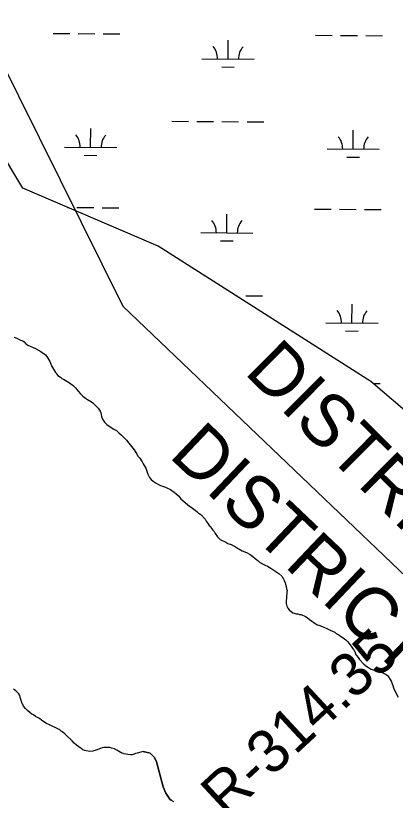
# Model space of a CAD drawing. Extents: x 3172231 to 3210228, y 940198 to 965780.
# Drawn here: x 3194127 to 3194853, y 949300 to 950801 of the extents above; entities that cross this region are included whole.
import ezdxf

# ---------------------------------------------------------------- set-up
doc = ezdxf.new("R2010")
doc.units = 0
for name, color, linetype in [('V-RIVR-RANG-IDEN', 7, 'Continuous'), ('V-SITE-VEGE', 7, 'Continuous'), ('V-TOPO-BNDY', 7, 'Continuous'), ('V-TOPO-GNAM-IDEN', 7, 'Continuous'), ('V-TOPO-SHOR', 7, 'Continuous'), ('V-WETL-SWMP', 7, 'Continuous')]:
    doc.layers.add(name, color=color, linetype=linetype)

msp = doc.modelspace()

# ---------------------------------------------------------------- linework, layer by layer
at = {"layer": 'V-SITE-VEGE'}
for p, q in [((3194124.25, 950186.368), (3194129.438, 950184.349)), ((3194129.438, 950184.349), (3194136.364, 950180.624)), ((3194136.364, 950180.624), (3194140.515, 950178.94)), ((3194140.515, 950178.94), (3194143.29, 950176.898)), ((3194143.29, 950176.898), (3194146.77, 950173.484)), ((3194146.77, 950173.484), (3194150.237, 950171.107)), ((3194150.237, 950171.107), (3194165.118, 950164.352)), ((3194165.118, 950164.352), (3194175.159, 950158.933)), ((3194175.159, 950158.933), (3194181.408, 950154.168)), ((3194181.408, 950154.168), (3194183.839, 950152.124)), ((3194183.839, 950152.124), (3194186.626, 950149.048)), ((3194186.626, 950149.048), (3194192.223, 950139.797)), ((3194192.223, 950139.797), (3194195.748, 950131.216)), ((3194195.748, 950131.216), (3194197.505, 950127.785)), ((3194197.505, 950127.785), (3194201.351, 950121.619)), ((3194201.351, 950121.619), (3194203.448, 950118.537)), ((3194203.448, 950118.537), (3194204.843, 950116.826)), ((3194204.843, 950116.826), (3194205.197, 950115.796)), ((3194205.197, 950115.796), (3194207.978, 950113.066)), ((3194207.978, 950113.066), (3194212.492, 950109.319)), ((3194212.492, 950109.319), (3194215.269, 950107.277)), ((3194215.269, 950107.277), (3194218.73, 950105.585)), ((3194218.73, 950105.585), (3194228.086, 950100.16)), ((3194228.086, 950100.16), (3194232.593, 950097.1)), ((3194232.593, 950097.1), (3194237.105, 950093.696)), ((3194237.105, 950093.696), (3194239.542, 950090.962)), ((3194239.542, 950090.962), (3194242.321, 950088.576)), ((3194242.321, 950088.576), (3194244.07, 950085.836)), ((3194244.07, 950085.836), (3194246.51, 950082.76)), ((3194246.51, 950082.76), (3194251.036, 950077.632)), ((3194251.036, 950077.632), (3194255.56, 950073.196)), ((3194255.56, 950073.196), (3194260.417, 950069.45)), ((3194260.417, 950069.45), (3194264.577, 950066.732)), ((3194264.577, 950066.732), (3194272.198, 950062.667)), ((3194272.198, 950062.667), (3194274.629, 950060.623)), ((3194274.629, 950060.623), (3194282.976, 950052.429)), ((3194282.976, 950052.429), (3194285.063, 950050.039)), ((3194285.063, 950050.039), (3194288.907, 950044.217)), ((3194288.907, 950044.217), (3194289.626, 950041.122)), ((3194289.626, 950041.122), (3194290.689, 950038.032)), ((3194290.689, 950038.032), (3194291.412, 950034.247)), ((3194291.412, 950034.247), (3194293.185, 950029.096)), ((3194293.185, 950029.096), (3194296.686, 950023.27)), ((3194296.686, 950023.27), (3194301.203, 950019.178)), ((3194301.203, 950019.178), (3194305.715, 950015.774)), ((3194305.715, 950015.774), (3194315.068, 950010.349)), ((3194315.068, 950010.349), (3194319.924, 950007.291)), ((3194319.924, 950007.291), (3194324.096, 950003.195)), ((3194324.096, 950003.195), (3194329.652, 949998.423)), ((3194329.652, 949998.423), (3194332.437, 949995.349)), ((3194332.437, 949995.349), (3194339.046, 949988.863)), ((3194339.046, 949988.863), (3194343.577, 949983.391)), ((3194343.577, 949983.391), (3194353.692, 949970.392)), ((3194353.692, 949970.392), (3194358.932, 949962.518)), ((3194358.932, 949962.518), (3194361.388, 949958.059)), ((3194361.388, 949958.059), (3194364.523, 949954.299)), ((3194364.523, 949954.299), (3194368.72, 949947.793)), ((3194368.72, 949947.793), (3194370.827, 949943.674)), ((3194370.827, 949943.674), (3194375.722, 949935.796)), ((3194375.722, 949935.796), (3194379.969, 949923.776)), ((3194379.969, 949923.776), (3194382.781, 949917.943)), ((3194382.781, 949917.943), (3194386.267, 949913.499)), ((3194386.267, 949913.499), (3194389.738, 949910.773)), ((3194389.738, 949910.773), (3194395.635, 949906.693)), ((3194395.635, 949906.693), (3194400.136, 949904.324)), ((3194400.136, 949904.324), (3194403.943, 949902.634)), ((3194403.943, 949902.634), (3194413.622, 949899.28)), ((3194413.622, 949899.28), (3194417.432, 949897.248)), ((3194417.432, 949897.248), (3194422.967, 949894.891)), ((3194422.967, 949894.891), (3194429.906, 949889.783)), ((3194429.906, 949889.783), (3194433.035, 949886.711)), ((3194433.035, 949886.711), (3194438.243, 949882.625)), ((3194438.243, 949882.625), (3194440.687, 949879.205)), ((3194440.687, 949879.205), (3194443.122, 949876.813)), ((3194443.122, 949876.813), (3194455.285, 949865.899)), ((3194455.285, 949865.899), (3194459.446, 949862.838)), ((3194459.446, 949862.838), (3194462.567, 949860.8)), ((3194462.567, 949860.8), (3194467.427, 949857.054)), ((3194467.427, 949857.054), (3194470.198, 949855.358)), ((3194470.198, 949855.358), (3194474.366, 949851.95)), ((3194474.366, 949851.95), (3194476.801, 949849.56)), ((3194476.801, 949849.56), (3194478.185, 949848.885)), ((3194478.185, 949848.885), (3194480.96, 949846.845)), ((3194480.96, 949846.845), (3194489.316, 949837.619)), ((3194489.316, 949837.619), (3194491.071, 949834.188)), ((3194491.071, 949834.188), (3194494.907, 949829.056)), ((3194494.907, 949829.056), (3194497.007, 949825.976)), ((3194497.007, 949825.976), (3194499.444, 949823.586)), ((3194499.444, 949823.586), (3194501.891, 949819.471)), ((3194501.891, 949819.471), (3194504.328, 949816.739)), ((3194504.328, 949816.739), (3194506.763, 949814.349)), ((3194506.763, 949814.349), (3194508.52, 949810.577)), ((3194508.52, 949810.577), (3194512.715, 949804.412)), ((3194512.715, 949804.412), (3194517.929, 949799.292)), ((3194517.929, 949799.292), (3194528.662, 949793.879)), ((3194528.662, 949793.879), (3194532.82, 949791.506)), ((3194532.82, 949791.506), (3194539.042, 949789.497)), ((3194539.042, 949789.497), (3194544.928, 949786.449)), ((3194544.928, 949786.449), (3194545.278, 949786.109)), ((3194545.278, 949786.109), (3194549.087, 949783.734)), ((3194549.087, 949783.734), (3194560.171, 949777.633)), ((3194560.171, 949777.633), (3194568.132, 949773.918)), ((3194568.132, 949773.918), (3194575.402, 949770.194)), ((3194575.402, 949770.194), (3194580.606, 949766.455)), ((3194580.606, 949766.455), (3194584.776, 949762.703)), ((3194584.776, 949762.703), (3194589.98, 949758.961)), ((3194589.98, 949758.961), (3194593.111, 949755.889)), ((3194593.111, 949755.889), (3194598.999, 949752.498)), ((3194598.999, 949752.498), (3194604.191, 949750.134)), ((3194604.191, 949750.134), (3194608.692, 949747.765)), ((3194608.692, 949747.765), (3194614.928, 949744.031)), ((3194614.928, 949744.031), (3194630.186, 949733.836)), ((3194630.186, 949733.836), (3194635.746, 949728.72)), ((3194635.746, 949728.72), (3194638.546, 949724.268)), ((3194638.546, 949724.268), (3194640.303, 949720.493)), ((3194640.303, 949720.493), (3194642.068, 949716.031)), ((3194642.068, 949716.031), (3194644.202, 949708.814)), ((3194644.202, 949708.814), (3194644.929, 949704.685)), ((3194644.929, 949704.685), (3194645.996, 949701.248)), ((3194645.996, 949701.248), (3194645.335, 949698.142)), ((3194645.335, 949698.142), (3194644.477, 949679.527)), ((3194644.477, 949679.527), (3194644.506, 949676.427)), ((3194644.506, 949676.427), (3194645.585, 949671.612)), ((3194645.585, 949671.612), (3194647.69, 949667.495)), ((3194647.69, 949667.495), (3194649.783, 949664.759)), ((3194649.783, 949664.759), (3194656.728, 949658.965)), ((3194656.728, 949658.965), (3194659.837, 949658.306)), ((3194659.837, 949658.306), (3194663.294, 949656.96)), ((3194663.294, 949656.96), (3194666.399, 949656.645)), ((3194666.399, 949656.645), (3194669.508, 949655.637)), ((3194669.508, 949655.637), (3194672.612, 949655.324)), ((3194672.612, 949655.324), (3194680.919, 949651.611)), ((3194680.919, 949651.611), (3194684.382, 949649.575)), ((3194684.382, 949649.575), (3194688.55, 949646.169)), ((3194688.55, 949646.169), (3194693.406, 949642.77)), ((3194693.406, 949642.77), (3194696.877, 949640.046)), ((3194696.877, 949640.046), (3194703.809, 949635.63)), ((3194703.809, 949635.63), (3194706.916, 949634.971)), ((3194706.916, 949634.971), (3194715.215, 949631.946)), ((3194715.215, 949631.946), (3194723.177, 949627.887)), ((3194723.177, 949627.887), (3194728.365, 949625.868)), ((3194728.365, 949625.868), (3194732.522, 949623.494)), ((3194732.522, 949623.494), (3194737.024, 949621.469)), ((3194737.024, 949621.469), (3194739.797, 949619.427)), ((3194739.797, 949619.427), (3194744.647, 949616.715)), ((3194744.647, 949616.715), (3194748.114, 949614.335)), ((3194748.114, 949614.335), (3194751.579, 949612.3)), ((3194751.579, 949612.3), (3194755.743, 949609.236)), ((3194755.743, 949609.236), (3194758.522, 949606.854)), ((3194758.522, 949606.854), (3194761.303, 949604.122)), ((3194761.303, 949604.122), (3194764.441, 949600.36)), ((3194764.441, 949600.36), (3194770.023, 949592.831)), ((3194770.023, 949592.831), (3194772.123, 949589.405)), ((3194772.123, 949589.405), (3194774.558, 949587.015)), ((3194774.558, 949587.015), (3194776.319, 949582.896)), ((3194776.319, 949582.896), (3194777.038, 949579.806)), ((3194777.038, 949579.806), (3194778.787, 949577.064)), ((3194778.787, 949577.064), (3194781.922, 949573.302)), ((3194781.922, 949573.302), (3194784.714, 949569.537)), ((3194784.714, 949569.537), (3194792.721, 949560.653)), ((3194792.721, 949560.653), (3194798.622, 949556.229)), ((3194798.622, 949556.229), (3194806.943, 949550.792)), ((3194806.943, 949550.792), (3194810.398, 949549.793)), ((3194810.398, 949549.793), (3194817.301, 949548.478)), ((3194817.301, 949548.478), (3194828.717, 949543.759)), ((3194828.717, 949543.759), (3194830.441, 949543.432)), ((3194830.441, 949543.432), (3194835.287, 949541.064)), ((3194835.287, 949541.064), (3194837.722, 949538.676)), ((3194837.722, 949538.676), (3194839.815, 949536.284)), ((3194839.815, 949536.284), (3194842.959, 949531.488)), ((3194842.959, 949531.488), (3194844.714, 949528.059)), ((3194844.714, 949528.059), (3194848.241, 949519.476)), ((3194127.125, 949509.642), (3194122.962, 949512.703)), ((3194130.601, 949506.572), (3194127.125, 949509.642)), ((3194133.04, 949503.496), (3194130.601, 949506.572)), ((3194848.241, 949519.476), (3194849.312, 949515.351)), ((3194849.312, 949515.351), (3194850.719, 949512.263)), ((3194850.719, 949512.263), (3194858.096, 949497.515)), ((3194135.137, 949500.411), (3194133.04, 949503.496)), ((3194136.571, 949494.566), (3194135.137, 949500.411)), ((3194137.294, 949490.784), (3194136.571, 949494.566)), ((3194138.709, 949487.007), (3194137.294, 949490.784)), ((3194142.215, 949480.492), (3194138.709, 949487.007)), ((3194146.049, 949475.704), (3194142.215, 949480.492)), ((3194149.879, 949471.604), (3194146.049, 949475.704)), ((3194155.089, 949467.174), (3194149.879, 949471.604)), ((3194157.864, 949465.132), (3194155.089, 949467.174)), ((3194160.981, 949463.439), (3194157.864, 949465.132)), ((3194164.794, 949460.719), (3194160.981, 949463.439)), ((3194168.61, 949458.341), (3194164.794, 949460.719)), ((3194172.419, 949456.31), (3194168.61, 949458.341)), ((3194176.935, 949452.562), (3194172.419, 949456.31)), ((3194180.052, 949450.866), (3194176.935, 949452.562)), ((3194184.904, 949447.81), (3194180.052, 949450.866)), ((3194192.866, 949443.751), (3194184.904, 949447.81)), ((3194207.747, 949436.999), (3194192.866, 949443.751)), ((3194211.214, 949434.619), (3194207.747, 949436.999)), ((3194214.69, 949431.549), (3194211.214, 949434.619)), ((3194217.809, 949429.512), (3194214.69, 949431.549)), ((3194220.932, 949427.13), (3194217.809, 949429.512)), ((3194223.711, 949424.742), (3194220.932, 949427.13)), ((3194234.84, 949413.82), (3194223.711, 949424.742)), ((3194239.018, 949409.382), (3194234.84, 949413.82)), ((3194243.188, 949405.628), (3194239.018, 949409.382)), ((3194247.695, 949402.568), (3194243.188, 949405.628)), ((3194252.205, 949399.164), (3194247.695, 949402.568)), ((3194295.606, 949400.948), (3194292.512, 949400.231)), ((3194307.321, 949401.059), (3194295.606, 949400.948)), ((3194310.432, 949400.053), (3194307.321, 949401.059)), ((3194255.674, 949396.784), (3194252.205, 949399.164)), ((3194258.443, 949395.433), (3194255.674, 949396.784)), ((3194261.554, 949394.427), (3194258.443, 949395.433)), ((3194269.144, 949393.465), (3194261.554, 949394.427)), ((3194274.309, 949393.858), (3194269.144, 949393.465)), ((3194281.18, 949395.99), (3194274.309, 949393.858)), ((3194289.075, 949399.164), (3194281.18, 949395.99)), ((3194292.512, 949400.231), (3194289.075, 949399.164)), ((3194315.957, 949398.726), (3194310.432, 949400.053)), ((3194320.463, 949396.012), (3194315.957, 949398.726)), ((3194326.703, 949391.937), (3194320.463, 949396.012)), ((3194330.164, 949390.245), (3194326.703, 949391.937)), ((3194332.927, 949389.582), (3194330.164, 949390.245)), ((3194333.275, 949389.24), (3194332.927, 949389.582)), ((3194337.764, 949388.248), (3194333.275, 949389.24)), ((3194341.557, 949387.941), (3194337.764, 949388.248)), ((3194346.735, 949386.954), (3194341.557, 949387.941)), ((3194349.831, 949387.329), (3194346.735, 949386.954)), ((3194353.616, 949388.052), (3194349.831, 949387.329)), ((3194356.36, 949389.457), (3194353.616, 949388.052)), ((3194359.451, 949390.52), (3194356.36, 949389.457)), ((3194366.33, 949391.961), (3194359.451, 949390.52)), ((3194370.95, 949393.37), (3194366.33, 949391.961)), ((3194384.317, 949390.163), (3194370.95, 949393.37)), ((3194392.409, 949382.145), (3194384.317, 949390.163)), ((3194396.29, 949373.538), (3194392.409, 949382.145)), ((3194409.373, 949325.844), (3194396.29, 949373.538)), ((3194414.413, 949313.658), (3194409.373, 949325.844)), ((3194421.681, 949302.505), (3194414.413, 949313.658)), ((3194424.364, 949300.086), (3194421.681, 949302.505))]:
    msp.add_line(p, q, dxfattribs=at)
at = {"layer": 'V-TOPO-BNDY'}
for p, q in [((3192802.44, 953324.154), (3194332.024, 950245.511)), ((3194332.024, 950245.511), (3197716.878, 947007.215))]:
    msp.add_line(p, q, dxfattribs=at)
at = {"layer": 'V-TOPO-SHOR'}
for points in [[(3194124.25, 950186.368), (3194129.438, 950184.349), (3194136.364, 950180.624), (3194140.515, 950178.94), (3194143.29, 950176.898), (3194146.77, 950173.484), (3194150.237, 950171.107), (3194165.118, 950164.352), (3194175.159, 950158.933), (3194181.408, 950154.168), (3194183.839, 950152.124), (3194186.624, 950149.048), (3194192.223, 950139.797), (3194195.75, 950131.216), (3194197.505, 950127.785), (3194201.351, 950121.619), (3194203.448, 950118.537), (3194204.843, 950116.826), (3194205.197, 950115.796), (3194207.978, 950113.066), (3194212.492, 950109.319), (3194215.269, 950107.277), (3194218.73, 950105.585), (3194228.086, 950100.16), (3194232.593, 950097.1), (3194237.105, 950093.696), (3194239.542, 950090.962), (3194242.321, 950088.576), (3194244.07, 950085.836), (3194246.51, 950082.758), (3194251.038, 950077.632), (3194255.56, 950073.196), (3194260.417, 950069.45), (3194264.577, 950066.732), (3194272.198, 950062.667), (3194274.629, 950060.623), (3194282.974, 950052.431), (3194285.063, 950050.039), (3194288.909, 950044.217), (3194289.626, 950041.122), (3194290.689, 950038.032), (3194291.414, 950034.247), (3194293.185, 950029.096), (3194296.686, 950023.27), (3194301.203, 950019.178), (3194305.715, 950015.774)], [(3194305.715, 950015.774), (3194315.068, 950010.349), (3194319.922, 950007.291), (3194324.096, 950003.195), (3194329.652, 949998.423), (3194332.437, 949995.349), (3194339.046, 949988.863), (3194343.577, 949983.391), (3194353.692, 949970.392), (3194358.932, 949962.518), (3194361.388, 949958.059), (3194364.523, 949954.299), (3194368.72, 949947.791), (3194370.825, 949943.676), (3194375.722, 949935.796), (3194379.969, 949923.776), (3194382.781, 949917.943), (3194386.267, 949913.497), (3194389.738, 949910.773), (3194395.635, 949906.693), (3194400.136, 949904.324), (3194403.943, 949902.634), (3194413.622, 949899.28), (3194417.432, 949897.248), (3194422.967, 949894.889), (3194429.906, 949889.783), (3194433.035, 949886.711), (3194438.243, 949882.625), (3194440.687, 949879.203), (3194443.122, 949876.813), (3194455.285, 949865.899), (3194459.446, 949862.838), (3194462.567, 949860.8), (3194467.427, 949857.054), (3194470.198, 949855.358), (3194474.366, 949851.95), (3194476.801, 949849.56), (3194478.185, 949848.885), (3194480.96, 949846.845), (3194489.316, 949837.619), (3194491.071, 949834.188), (3194494.909, 949829.056), (3194497.007, 949825.974), (3194499.442, 949823.586), (3194501.891, 949819.473), (3194504.328, 949816.739), (3194506.763, 949814.349), (3194508.52, 949810.577), (3194512.715, 949804.412), (3194517.931, 949799.292), (3194528.662, 949793.879), (3194532.82, 949791.506), (3194539.042, 949789.497), (3194544.928, 949786.449), (3194545.276, 949786.109), (3194549.087, 949783.734), (3194560.171, 949777.635), (3194568.132, 949773.918), (3194575.402, 949770.194), (3194580.606, 949766.455), (3194584.776, 949762.703), (3194589.98, 949758.961), (3194593.111, 949755.889), (3194598.999, 949752.498), (3194604.191, 949750.134), (3194608.692, 949747.765), (3194614.928, 949744.031), (3194630.186, 949733.836), (3194635.746, 949728.72), (3194638.546, 949724.268), (3194640.303, 949720.493), (3194642.068, 949716.031), (3194644.202, 949708.814), (3194644.929, 949704.685), (3194645.996, 949701.248), (3194645.335, 949698.142), (3194644.477, 949679.527), (3194644.506, 949676.427), (3194645.585, 949671.612), (3194647.69, 949667.495), (3194649.783, 949664.759), (3194656.728, 949658.965), (3194659.837, 949658.306), (3194663.294, 949656.96), (3194666.399, 949656.645), (3194669.51, 949655.639), (3194672.612, 949655.324), (3194672.612, 949655.324), (3194680.919, 949651.611), (3194684.382, 949649.575), (3194688.55, 949646.169), (3194693.406, 949642.77), (3194696.877, 949640.046), (3194703.809, 949635.63), (3194706.916, 949634.971), (3194715.215, 949631.946), (3194723.177, 949627.887), (3194728.365, 949625.868), (3194732.522, 949623.494), (3194737.022, 949621.469), (3194739.797, 949619.427)], [(3194739.797, 949619.427), (3194744.647, 949616.715), (3194748.116, 949614.335), (3194751.579, 949612.3), (3194755.743, 949609.238), (3194758.522, 949606.852), (3194761.303, 949604.122), (3194764.441, 949600.36), (3194770.023, 949592.831), (3194772.123, 949589.405), (3194774.558, 949587.015), (3194776.319, 949582.896), (3194777.038, 949579.804), (3194778.787, 949577.064), (3194781.922, 949573.302), (3194784.714, 949569.537), (3194792.721, 949560.653), (3194798.622, 949556.229), (3194806.943, 949550.792), (3194810.398, 949549.793), (3194817.301, 949548.478), (3194828.717, 949543.759), (3194830.441, 949543.432), (3194835.287, 949541.064), (3194837.722, 949538.676), (3194839.813, 949536.284), (3194842.959, 949531.488), (3194844.714, 949528.059), (3194848.241, 949519.476), (3194849.312, 949515.351), (3194850.719, 949512.263), (3194858.094, 949497.515)], [(3194370.95, 949393.37), (3194366.33, 949391.961), (3194359.451, 949390.52), (3194356.36, 949389.457), (3194353.616, 949388.052), (3194349.833, 949387.329), (3194346.735, 949386.954), (3194341.557, 949387.939), (3194337.764, 949388.248), (3194333.275, 949389.24), (3194332.927, 949389.582), (3194330.164, 949390.245), (3194326.703, 949391.937), (3194320.463, 949396.012), (3194315.957, 949398.726), (3194310.432, 949400.053), (3194307.321, 949401.059), (3194295.606, 949400.948), (3194292.512, 949400.231), (3194289.075, 949399.164), (3194281.18, 949395.99), (3194274.309, 949393.858), (3194269.144, 949393.465), (3194261.554, 949394.427), (3194258.443, 949395.433), (3194255.674, 949396.784), (3194252.205, 949399.164), (3194247.695, 949402.568), (3194243.188, 949405.628), (3194239.018, 949409.38), (3194234.84, 949413.82), (3194223.711, 949424.742), (3194220.932, 949427.13), (3194217.809, 949429.512), (3194214.69, 949431.549), (3194211.214, 949434.619), (3194207.747, 949436.999), (3194192.866, 949443.751), (3194184.904, 949447.81), (3194180.052, 949450.866), (3194176.935, 949452.562), (3194172.419, 949456.31), (3194168.61, 949458.341), (3194164.796, 949460.719), (3194160.981, 949463.439), (3194157.864, 949465.132), (3194155.089, 949467.174), (3194149.879, 949471.604), (3194146.049, 949475.704), (3194142.215, 949480.492), (3194138.709, 949487.007), (3194137.294, 949490.784), (3194136.571, 949494.566), (3194135.137, 949500.411), (3194133.04, 949503.493), (3194130.601, 949506.572), (3194127.125, 949509.642), (3194122.962, 949512.703)], [(3194370.95, 949393.37), (3194384.317, 949390.163), (3194392.409, 949382.145), (3194396.29, 949373.536), (3194409.373, 949325.844), (3194414.413, 949313.658), (3194421.681, 949302.503), (3194424.364, 949300.088), (3194428.616, 949297.641)]]:
    msp.add_lwpolyline(points, dxfattribs=at)
at = {"layer": 'V-WETL-SWMP'}
for p, q in [((3194140.824, 950470.858), (3193919.041, 950840.648)), ((3194198.521, 950767.073), (3194230.52, 950766.855)), ((3194246.52, 950766.746), (3194278.519, 950766.528)), ((3194294.519, 950766.419), (3194326.518, 950766.201)), ((3194533.041, 950718.365), (3194533.286, 950754.364)), ((3194700.418, 950763.656), (3194732.417, 950763.438)), ((3194748.416, 950763.329), (3194780.416, 950763.112)), ((3194796.415, 950763.003), (3194828.415, 950762.785)), ((3194483.043, 950718.705), (3194583.04, 950718.024)), ((3194520.937, 950703.016), (3194544.936, 950702.852)), ((3194425.383, 950599.024), (3194457.382, 950598.806)), ((3194473.381, 950598.697), (3194505.381, 950598.479)), ((3194521.38, 950598.37), (3194553.38, 950598.152)), ((3194569.379, 950598.043), (3194601.378, 950597.826)), ((3194270.449, 950549.335), (3194270.694, 950585.334)), ((3194772.345, 950545.919), (3194772.59, 950581.918)), ((3194220.45, 950549.675), (3194320.448, 950548.995)), ((3194722.346, 950546.259), (3194822.344, 950545.578)), ((3194258.344, 950533.986), (3194282.343, 950533.823)), ((3194760.24, 950530.57), (3194784.24, 950530.406)), ((3194399.57, 950359.921), (3194140.824, 950470.858)), ((3194226.322, 950434.201), (3194228.256, 950434.188)), ((3194244.256, 950434.079), (3194276.255, 950433.861)), ((3194292.254, 950433.752), (3194324.254, 950433.534)), ((3194530.777, 950385.697), (3194531.022, 950421.696)), ((3194698.153, 950430.989), (3194730.152, 950430.771)), ((3194746.152, 950430.662), (3194778.151, 950430.444)), ((3194794.151, 950430.335), (3194826.15, 950430.118)), ((3194480.778, 950386.038), (3194580.776, 950385.357)), ((3194518.672, 950370.348), (3194542.672, 950370.185)), ((3194806.172, 950101.067), (3194399.57, 950359.921)), ((3194547.873, 950265.507), (3194551.115, 950265.485)), ((3194567.115, 950265.376), (3194599.114, 950265.158)), ((3194770.081, 950213.251), (3194770.326, 950249.25)), ((3194720.082, 950213.592), (3194820.079, 950212.911)), ((3194757.976, 950197.902), (3194781.975, 950197.739)), ((3195064.919, 949879.193), (3194806.172, 950101.067)), ((3194810.282, 950097.543), (3194823.886, 950097.45))]:
    msp.add_line(p, q, dxfattribs=at)
for centre, start, end in [((3194477.803, 950719.215), 358.838165, 40.381824), ((3194588.286, 950718.463), 138.838162, 180.381821), ((3194215.21, 950550.186), 358.838165, 40.381824), ((3194325.694, 950549.434), 138.838162, 180.381821), ((3194717.107, 950546.769), 358.838165, 40.381824), ((3194827.59, 950546.017), 138.838162, 180.381821), ((3194475.538, 950386.548), 358.838165, 40.381824), ((3194586.022, 950385.796), 138.838162, 180.381821), ((3194714.842, 950214.102), 358.838165, 40.381824), ((3194825.325, 950213.35), 138.838162, 180.381821)]:
    msp.add_arc(centre, 35.246, start, end, dxfattribs=at)

# ---------------------------------------------------------------- texts
at = {"layer": 'V-RIVR-RANG-IDEN'}
msp.add_text('R-314.35', height=82.9998, rotation=42.826497, dxfattribs=at).set_placement((3194529.934, 949263.813))
at = {"layer": 'V-TOPO-GNAM-IDEN'}
for rotation, p in [(315.174813, (3194562.298, 950118.02)), (316.502046, (3194418.095, 949958.13))]:
    msp.add_text('DISTRICT', height=99.9998, rotation=rotation, dxfattribs=at).set_placement(p)

doc.saveas('drawing.dxf')
